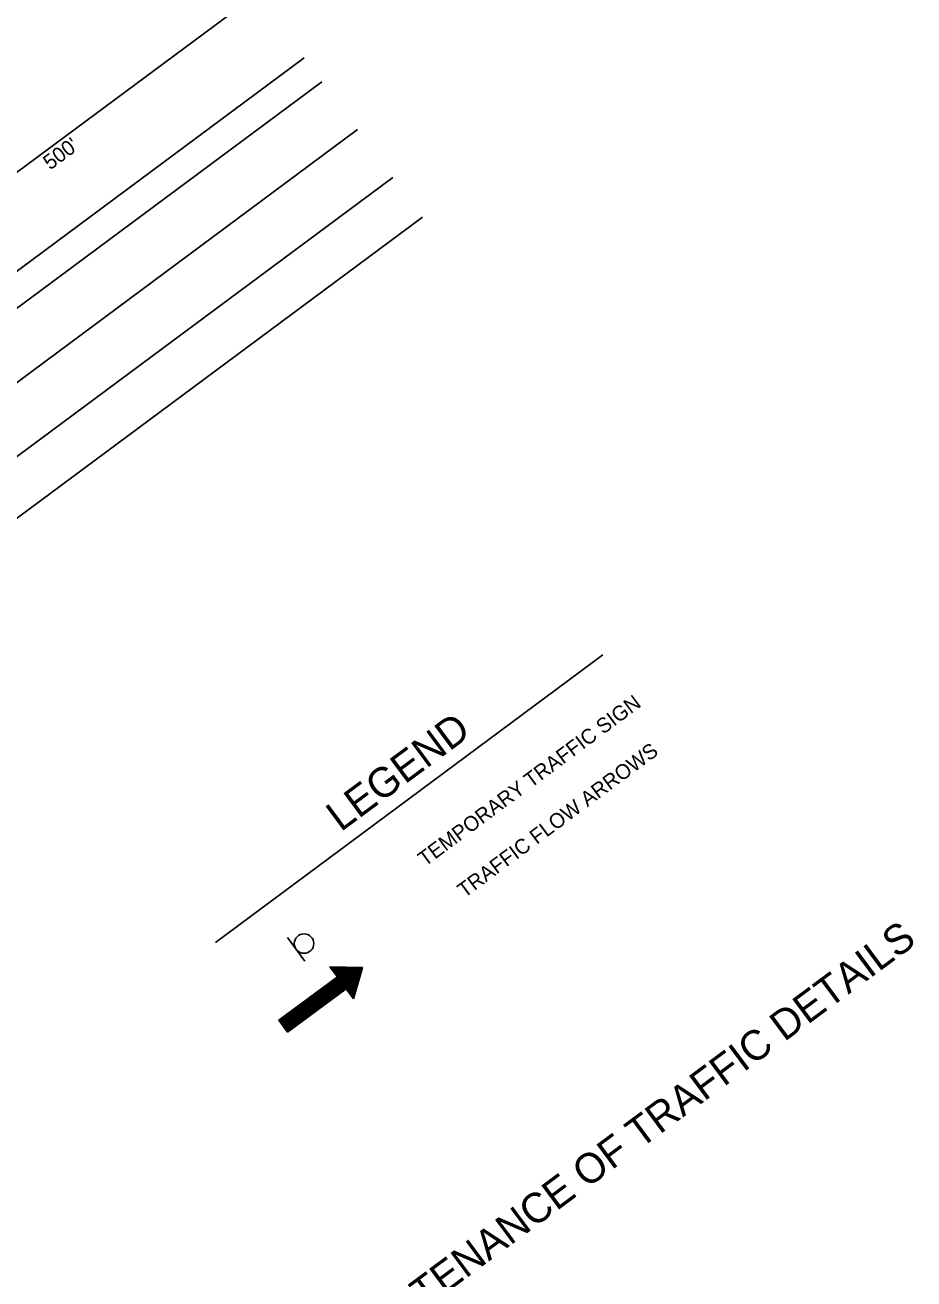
# Model space of a CAD drawing. Extents: x -238 to 1487, y -1123 to 446.
# Drawn here: x 1130 to 1487, y -485 to 19 of the extents above; entities that cross this region are included whole.
import ezdxf

# ---------------------------------------------------------------- set-up
doc = ezdxf.new("R2010")
doc.units = 0
for name, color, linetype in [('R_Border Prem', 7, 'Continuous'), ('R_Draft', 7, 'Continuous'), ('STAMP', 7, 'Continuous')]:
    doc.layers.add(name, color=color, linetype=linetype)

msp = doc.modelspace()

# ---------------------------------------------------------------- linework, layer by layer
at = {"layer": 'R_Border Prem'}
for p, q in [((1206.6, -349.6), (1362.29, -234)), ((1252.61, -359.52), (1252.62, -359.44)), ((1252.7, -359.63), (1252.72, -359.45)), ((1252.78, -359.74), (1252.83, -359.45)), ((1252.87, -359.86), (1252.93, -359.45)), ((1252.95, -359.97), (1253.03, -359.45)), ((1253.03, -360.08), (1253.13, -359.45)), ((1253.12, -360.2), (1253.23, -359.46)), ((1253.2, -360.31), (1253.33, -359.46)), ((1253.29, -360.42), (1253.43, -359.46)), ((1253.37, -360.54), (1253.53, -359.46)), ((1253.46, -360.65), (1253.63, -359.46)), ((1253.54, -360.77), (1253.73, -359.46)), ((1253.62, -360.88), (1253.83, -359.47)), ((1253.71, -360.99), (1253.93, -359.47)), ((1253.79, -361.11), (1254.04, -359.47)), ((1253.88, -361.22), (1254.14, -359.47)), ((1253.96, -361.33), (1254.24, -359.47)), ((1254.05, -361.45), (1254.34, -359.48)), ((1254.13, -361.56), (1254.44, -359.48)), ((1254.21, -361.67), (1254.54, -359.48)), ((1254.3, -361.79), (1254.64, -359.48)), ((1254.34, -371.79), (1256.15, -359.51)), ((1254.38, -361.9), (1254.74, -359.48)), ((1254.45, -371.7), (1256.25, -359.51)), ((1254.47, -362.01), (1254.84, -359.48)), ((1254.55, -362.13), (1254.94, -359.49)), ((1254.56, -371.62), (1256.35, -359.51)), ((1254.64, -362.24), (1255.04, -359.49)), ((1254.68, -371.54), (1256.45, -359.51)), ((1254.72, -362.35), (1255.14, -359.49)), ((1254.79, -371.45), (1256.56, -359.52)), ((1254.81, -362.47), (1255.24, -359.49)), ((1254.89, -362.58), (1255.35, -359.49)), ((1254.91, -371.37), (1256.66, -359.52)), ((1254.97, -362.7), (1255.45, -359.5)), ((1255.02, -371.28), (1256.76, -359.52)), ((1255.06, -362.81), (1255.55, -359.5)), ((1255.13, -371.2), (1256.86, -359.52)), ((1255.14, -362.92), (1255.65, -359.5)), ((1255.23, -363.04), (1255.75, -359.5)), ((1255.25, -371.11), (1256.96, -359.52)), ((1255.31, -363.15), (1255.85, -359.5)), ((1255.36, -371.03), (1257.06, -359.52)), ((1255.4, -363.26), (1255.95, -359.5)), ((1255.47, -370.95), (1257.16, -359.53)), ((1255.48, -363.38), (1256.05, -359.51)), ((1255.59, -370.86), (1257.26, -359.53)), ((1255.7, -370.78), (1257.36, -359.53)), ((1255.81, -370.69), (1257.46, -359.53)), ((1255.93, -370.61), (1257.56, -359.53)), ((1256.04, -370.52), (1257.66, -359.53)), ((1256.15, -370.44), (1257.77, -359.54)), ((1256.27, -370.36), (1257.87, -359.54)), ((1256.38, -370.27), (1257.97, -359.54)), ((1256.5, -370.19), (1258.07, -359.54)), ((1256.61, -370.1), (1258.17, -359.54)), ((1256.72, -370.02), (1258.27, -359.55)), ((1256.84, -369.93), (1258.37, -359.55)), ((1256.95, -369.85), (1258.47, -359.55)), ((1257.06, -369.77), (1258.57, -359.55)), ((1257.18, -369.68), (1258.67, -359.55)), ((1257.29, -369.6), (1258.77, -359.55)), ((1257.4, -369.51), (1258.87, -359.56)), ((1257.52, -369.43), (1258.98, -359.56)), ((1257.63, -369.34), (1259.08, -359.56)), ((1257.74, -369.26), (1259.18, -359.56)), ((1257.86, -369.18), (1259.28, -359.56)), ((1257.97, -369.09), (1259.38, -359.57)), ((1258.08, -369.01), (1259.48, -359.57)), ((1258.2, -368.92), (1259.58, -359.57)), ((1258.31, -368.84), (1259.68, -359.57)), ((1258.43, -368.75), (1259.78, -359.57)), ((1258.54, -368.67), (1259.88, -359.57)), ((1258.65, -368.59), (1259.98, -359.58)), ((1258.77, -368.5), (1260.08, -359.58)), ((1258.88, -368.42), (1260.19, -359.58)), ((1258.99, -368.33), (1260.29, -359.58)), ((1259.1, -368.26), (1260.39, -359.58)), ((1259.19, -368.37), (1260.49, -359.59)), ((1259.27, -368.49), (1260.59, -359.59)), ((1259.36, -368.6), (1260.69, -359.59)), ((1259.44, -368.71), (1260.79, -359.59)), ((1259.53, -368.83), (1260.89, -359.59)), ((1259.61, -368.94), (1260.99, -359.59)), ((1259.7, -369.05), (1261.09, -359.6)), ((1259.78, -369.17), (1261.19, -359.6)), ((1259.86, -369.28), (1261.29, -359.6)), ((1259.95, -369.39), (1261.39, -359.6)), ((1260.03, -369.51), (1261.5, -359.6)), ((1260.12, -369.62), (1261.6, -359.61)), ((1260.2, -369.74), (1261.7, -359.61)), ((1260.29, -369.85), (1261.8, -359.61)), ((1260.37, -369.96), (1261.9, -359.61)), ((1260.45, -370.08), (1262, -359.61)), ((1260.54, -370.19), (1262.1, -359.61)), ((1260.62, -370.3), (1262.2, -359.62)), ((1260.71, -370.42), (1262.3, -359.62)), ((1260.79, -370.53), (1262.4, -359.62)), ((1260.88, -370.64), (1262.5, -359.62)), ((1260.96, -370.76), (1262.6, -359.62)), ((1261.04, -370.87), (1262.71, -359.62)), ((1261.13, -370.98), (1262.81, -359.63)), ((1261.21, -371.1), (1262.91, -359.63)), ((1261.3, -371.21), (1263.01, -359.63)), ((1261.38, -371.32), (1263.11, -359.63)), ((1261.47, -371.44), (1263.21, -359.63)), ((1261.55, -371.55), (1263.31, -359.64)), ((1261.63, -371.67), (1263.41, -359.64)), ((1261.72, -371.78), (1263.51, -359.64)), ((1261.8, -371.89), (1263.61, -359.64)), ((1261.89, -372.01), (1263.71, -359.64)), ((1261.97, -372.12), (1263.81, -359.64)), ((1262.06, -372.23), (1263.92, -359.65)), ((1262.24, -371.66), (1264.02, -359.65)), ((1262.45, -370.92), (1264.12, -359.65)), ((1262.66, -370.17), (1264.22, -359.65)), ((1262.88, -369.42), (1264.32, -359.65)), ((1263.09, -368.67), (1264.42, -359.66)), ((1263.3, -367.92), (1264.52, -359.66)), ((1263.51, -367.17), (1264.62, -359.66)), ((1263.72, -366.42), (1264.72, -359.66)), ((1263.93, -365.67), (1264.82, -359.66)), ((1264.15, -364.92), (1264.92, -359.66)), ((1264.36, -364.18), (1265.02, -359.67)), ((1264.57, -363.43), (1265.13, -359.67)), ((1264.78, -362.68), (1265.23, -359.67)), ((1264.99, -361.93), (1265.33, -359.67)), ((1265.21, -361.18), (1265.43, -359.67)), ((1265.42, -360.43), (1265.53, -359.68)), ((1265.63, -359.68), (1265.63, -359.68)), ((1248.09, -376.43), (1249.33, -368.05)), ((1248.21, -376.34), (1249.44, -367.97)), ((1248.32, -376.26), (1249.56, -367.88)), ((1248.43, -376.17), (1249.67, -367.8)), ((1248.55, -376.09), (1249.78, -367.72)), ((1248.66, -376), (1249.9, -367.63)), ((1248.77, -375.92), (1250.01, -367.55)), ((1248.89, -375.84), (1250.12, -367.46)), ((1249, -375.75), (1250.24, -367.38)), ((1249.11, -375.67), (1250.35, -367.29)), ((1249.23, -375.58), (1250.47, -367.21)), ((1249.34, -375.5), (1250.58, -367.13)), ((1249.46, -375.41), (1250.69, -367.04)), ((1249.57, -375.33), (1250.81, -366.96)), ((1249.68, -375.25), (1250.92, -366.87)), ((1249.8, -375.16), (1251.03, -366.79)), ((1249.91, -375.08), (1251.15, -366.7)), ((1250.02, -374.99), (1251.26, -366.62)), ((1250.14, -374.91), (1251.37, -366.54)), ((1250.25, -374.82), (1251.49, -366.45)), ((1250.36, -374.74), (1251.6, -366.37)), ((1250.48, -374.66), (1251.71, -366.28)), ((1250.59, -374.57), (1251.83, -366.2)), ((1250.7, -374.49), (1251.94, -366.11)), ((1250.82, -374.4), (1252.05, -366.03)), ((1250.93, -374.32), (1252.17, -365.95)), ((1251.05, -374.23), (1252.28, -365.86)), ((1251.16, -374.15), (1252.4, -365.78)), ((1251.27, -374.07), (1252.51, -365.69)), ((1251.39, -373.98), (1252.62, -365.61)), ((1251.5, -373.9), (1252.74, -365.52)), ((1251.61, -373.81), (1252.85, -365.44)), ((1251.73, -373.73), (1252.96, -365.36)), ((1251.84, -373.64), (1253.08, -365.27)), ((1251.95, -373.56), (1253.19, -365.19)), ((1252.07, -373.48), (1253.3, -365.1)), ((1252.18, -373.39), (1253.42, -365.02)), ((1252.29, -373.31), (1253.53, -364.93)), ((1252.41, -373.22), (1253.64, -364.85)), ((1252.52, -373.14), (1253.76, -364.77)), ((1252.63, -373.05), (1253.87, -364.68)), ((1252.75, -372.97), (1253.99, -364.6)), ((1252.86, -372.89), (1254.1, -364.51)), ((1252.98, -372.8), (1254.21, -364.43)), ((1253.09, -372.72), (1254.33, -364.34)), ((1253.2, -372.63), (1254.44, -364.26)), ((1253.32, -372.55), (1254.55, -364.18)), ((1253.43, -372.46), (1254.67, -364.09)), ((1253.54, -372.38), (1254.78, -364.01)), ((1253.66, -372.29), (1254.89, -363.92)), ((1253.77, -372.21), (1255.01, -363.84)), ((1253.88, -372.13), (1255.12, -363.75)), ((1254, -372.04), (1255.23, -363.67)), ((1254.11, -371.96), (1255.35, -363.59)), ((1254.22, -371.87), (1255.46, -363.5)), ((1241.28, -381.48), (1242.52, -373.11)), ((1241.39, -381.4), (1242.63, -373.03)), ((1241.51, -381.32), (1242.74, -372.94)), ((1241.62, -381.23), (1242.86, -372.86)), ((1241.73, -381.15), (1242.97, -372.77)), ((1241.85, -381.06), (1243.09, -372.69)), ((1241.96, -380.98), (1243.2, -372.61)), ((1242.08, -380.89), (1243.31, -372.52)), ((1242.19, -380.81), (1243.43, -372.44)), ((1242.3, -380.73), (1243.54, -372.35)), ((1242.42, -380.64), (1243.65, -372.27)), ((1242.53, -380.56), (1243.77, -372.18)), ((1242.64, -380.47), (1243.88, -372.1)), ((1242.76, -380.39), (1243.99, -372.02)), ((1242.87, -380.3), (1244.11, -371.93)), ((1242.98, -380.22), (1244.22, -371.85)), ((1243.1, -380.14), (1244.33, -371.76)), ((1243.21, -380.05), (1244.45, -371.68)), ((1243.32, -379.97), (1244.56, -371.59)), ((1243.44, -379.88), (1244.67, -371.51)), ((1243.55, -379.8), (1244.79, -371.43)), ((1243.66, -379.71), (1244.9, -371.34)), ((1243.78, -379.63), (1245.02, -371.26)), ((1243.89, -379.55), (1245.13, -371.17)), ((1244.01, -379.46), (1245.24, -371.09)), ((1244.12, -379.38), (1245.36, -371)), ((1244.23, -379.29), (1245.47, -370.92)), ((1244.35, -379.21), (1245.58, -370.84)), ((1244.46, -379.12), (1245.7, -370.75)), ((1244.57, -379.04), (1245.81, -370.67)), ((1244.69, -378.96), (1245.92, -370.58)), ((1244.8, -378.87), (1246.04, -370.5)), ((1244.91, -378.79), (1246.15, -370.41)), ((1245.03, -378.7), (1246.26, -370.33)), ((1245.14, -378.62), (1246.38, -370.25)), ((1245.25, -378.53), (1246.49, -370.16)), ((1245.37, -378.45), (1246.6, -370.08)), ((1245.48, -378.37), (1246.72, -369.99)), ((1245.59, -378.28), (1246.83, -369.91)), ((1245.71, -378.2), (1246.95, -369.82)), ((1245.82, -378.11), (1247.06, -369.74)), ((1245.94, -378.03), (1247.17, -369.66)), ((1246.05, -377.94), (1247.29, -369.57)), ((1246.16, -377.86), (1247.4, -369.49)), ((1246.28, -377.78), (1247.51, -369.4)), ((1246.39, -377.69), (1247.63, -369.32)), ((1246.5, -377.61), (1247.74, -369.23)), ((1246.62, -377.52), (1247.85, -369.15)), ((1246.73, -377.44), (1247.97, -369.07)), ((1246.84, -377.35), (1248.08, -368.98)), ((1246.96, -377.27), (1248.19, -368.9)), ((1247.07, -377.18), (1248.31, -368.81)), ((1247.18, -377.1), (1248.42, -368.73)), ((1247.3, -377.02), (1248.54, -368.64)), ((1247.41, -376.93), (1248.65, -368.56)), ((1247.53, -376.85), (1248.76, -368.47)), ((1247.64, -376.76), (1248.88, -368.39)), ((1247.75, -376.68), (1248.99, -368.31)), ((1247.87, -376.59), (1249.1, -368.22)), ((1247.98, -376.51), (1249.22, -368.14)), ((1234.74, -384.68), (1235.7, -378.17)), ((1234.83, -384.79), (1235.82, -378.09)), ((1234.91, -384.91), (1235.93, -378)), ((1235, -385.02), (1236.05, -377.92)), ((1235.08, -385.13), (1236.16, -377.83)), ((1235.16, -385.25), (1236.27, -377.75)), ((1235.25, -385.36), (1236.39, -377.66)), ((1235.33, -385.47), (1236.5, -377.58)), ((1235.42, -385.59), (1236.61, -377.5)), ((1235.5, -385.7), (1236.73, -377.41)), ((1235.6, -385.7), (1236.84, -377.33)), ((1235.72, -385.62), (1236.95, -377.24)), ((1235.83, -385.53), (1237.07, -377.16)), ((1235.94, -385.45), (1237.18, -377.07)), ((1236.06, -385.36), (1237.29, -376.99)), ((1236.17, -385.28), (1237.41, -376.91)), ((1236.28, -385.19), (1237.52, -376.82)), ((1236.4, -385.11), (1237.64, -376.74)), ((1236.51, -385.03), (1237.75, -376.65)), ((1236.63, -384.94), (1237.86, -376.57)), ((1236.74, -384.86), (1237.98, -376.48)), ((1236.85, -384.77), (1238.09, -376.4)), ((1236.97, -384.69), (1238.2, -376.32)), ((1237.08, -384.6), (1238.32, -376.23)), ((1237.19, -384.52), (1238.43, -376.15)), ((1237.31, -384.44), (1238.54, -376.06)), ((1237.42, -384.35), (1238.66, -375.98)), ((1237.53, -384.27), (1238.77, -375.89)), ((1237.65, -384.18), (1238.88, -375.81)), ((1237.76, -384.1), (1239, -375.73)), ((1237.87, -384.01), (1239.11, -375.64)), ((1237.99, -383.93), (1239.22, -375.56)), ((1238.1, -383.85), (1239.34, -375.47)), ((1238.21, -383.76), (1239.45, -375.39)), ((1238.33, -383.68), (1239.57, -375.3)), ((1238.44, -383.59), (1239.68, -375.22)), ((1238.56, -383.51), (1239.79, -375.14)), ((1238.67, -383.42), (1239.91, -375.05)), ((1238.78, -383.34), (1240.02, -374.97)), ((1238.9, -383.26), (1240.13, -374.88)), ((1239.01, -383.17), (1240.25, -374.8)), ((1239.12, -383.09), (1240.36, -374.71)), ((1239.24, -383), (1240.47, -374.63)), ((1239.35, -382.92), (1240.59, -374.55)), ((1239.46, -382.83), (1240.7, -374.46)), ((1239.58, -382.75), (1240.81, -374.38)), ((1239.69, -382.66), (1240.93, -374.29)), ((1239.8, -382.58), (1241.04, -374.21)), ((1239.92, -382.5), (1241.15, -374.12)), ((1240.03, -382.41), (1241.27, -374.04)), ((1240.14, -382.33), (1241.38, -373.96)), ((1240.26, -382.24), (1241.5, -373.87)), ((1240.37, -382.16), (1241.61, -373.79)), ((1240.49, -382.07), (1241.72, -373.7)), ((1240.6, -381.99), (1241.84, -373.62)), ((1240.71, -381.91), (1241.95, -373.53)), ((1240.83, -381.82), (1242.06, -373.45)), ((1240.94, -381.74), (1242.18, -373.36)), ((1241.05, -381.65), (1242.29, -373.28)), ((1241.17, -381.57), (1242.4, -373.2)), ((1232.05, -381.04), (1232.07, -380.87)), ((1232.13, -381.16), (1232.19, -380.78)), ((1232.21, -381.27), (1232.3, -380.7)), ((1232.3, -381.39), (1232.41, -380.62)), ((1232.38, -381.5), (1232.53, -380.53)), ((1232.47, -381.61), (1232.64, -380.45)), ((1232.55, -381.73), (1232.75, -380.36)), ((1232.64, -381.84), (1232.87, -380.28)), ((1232.72, -381.95), (1232.98, -380.19)), ((1232.8, -382.07), (1233.09, -380.11)), ((1232.89, -382.18), (1233.21, -380.03)), ((1232.97, -382.29), (1233.32, -379.94)), ((1233.06, -382.41), (1233.43, -379.86)), ((1233.14, -382.52), (1233.55, -379.77)), ((1233.23, -382.63), (1233.66, -379.69)), ((1233.31, -382.75), (1233.77, -379.6)), ((1233.39, -382.86), (1233.89, -379.52)), ((1233.48, -382.97), (1234, -379.44)), ((1233.56, -383.09), (1234.12, -379.35)), ((1233.65, -383.2), (1234.23, -379.27)), ((1233.73, -383.32), (1234.34, -379.18)), ((1233.82, -383.43), (1234.46, -379.1)), ((1233.9, -383.54), (1234.57, -379.01)), ((1233.98, -383.66), (1234.68, -378.93)), ((1234.07, -383.77), (1234.8, -378.85)), ((1234.15, -383.88), (1234.91, -378.76)), ((1234.24, -384), (1235.02, -378.68)), ((1234.32, -384.11), (1235.14, -378.59)), ((1234.41, -384.22), (1235.25, -378.51)), ((1234.49, -384.34), (1235.36, -378.42)), ((1234.57, -384.45), (1235.48, -378.34)), ((1234.66, -384.56), (1235.59, -378.25))]:
    msp.add_line(p, q, dxfattribs=at)
at = {"layer": 'R_Draft'}
for p, q in [((1062.58, -87.49), (1223.15, 31.74)), ((1242.19, 6.1), (691.32, -402.94)), ((1249.33, -3.51), (698.46, -412.55)), ((1263.6, -22.73), (712.73, -431.77)), ((1277.87, -41.95), (727, -450.98)), ((1289.76, -57.96), (738.89, -467)), ((1252.56, -359.44), (1255.53, -363.45)), ((1252.56, -359.44), (1265.63, -359.68)), ((1252.56, -359.44), (1255.53, -363.45)), ((1252.56, -359.44), (1265.63, -359.68)), ((1265.63, -359.68), (1262.07, -372.26)), ((1265.63, -359.68), (1262.07, -372.26)), ((1255.53, -363.45), (1231.97, -380.95)), ((1255.53, -363.45), (1231.97, -380.94)), ((1259.1, -368.25), (1235.53, -385.75)), ((1259.1, -368.25), (1235.54, -385.75)), ((1259.1, -368.25), (1262.07, -372.26)), ((1259.1, -368.25), (1262.07, -372.26)), ((1231.97, -380.94), (1235.54, -385.75)), ((1231.97, -380.95), (1235.53, -385.75))]:
    msp.add_line(p, q, dxfattribs=at)
at = {"layer": 'STAMP'}
msp.add_line((1242.49, -357.16), (1235.49, -347.71), dxfattribs=at)
msp.add_circle((1242.14, -350.1), 3.92, dxfattribs=at)

# ---------------------------------------------------------------- texts
at = {"layer": 'R_Border Prem'}
for s, height, p in [("500'", 6, (1140.05, -39.22)), ('TEMPORARY TRAFFIC SIGN', 6, (1290.81, -319.31)), ('LEGEND', 12, (1256.91, -305.38)), ('TRAFFIC FLOW ARROWS', 6, (1306.71, -331.95)), ('MAINTENANCE OF TRAFFIC DETAILS', 12, (1258.47, -521.06))]:
    msp.add_text(s, height=height, rotation=36.5953, dxfattribs=at).set_placement(p)

doc.saveas('drawing.dxf')
